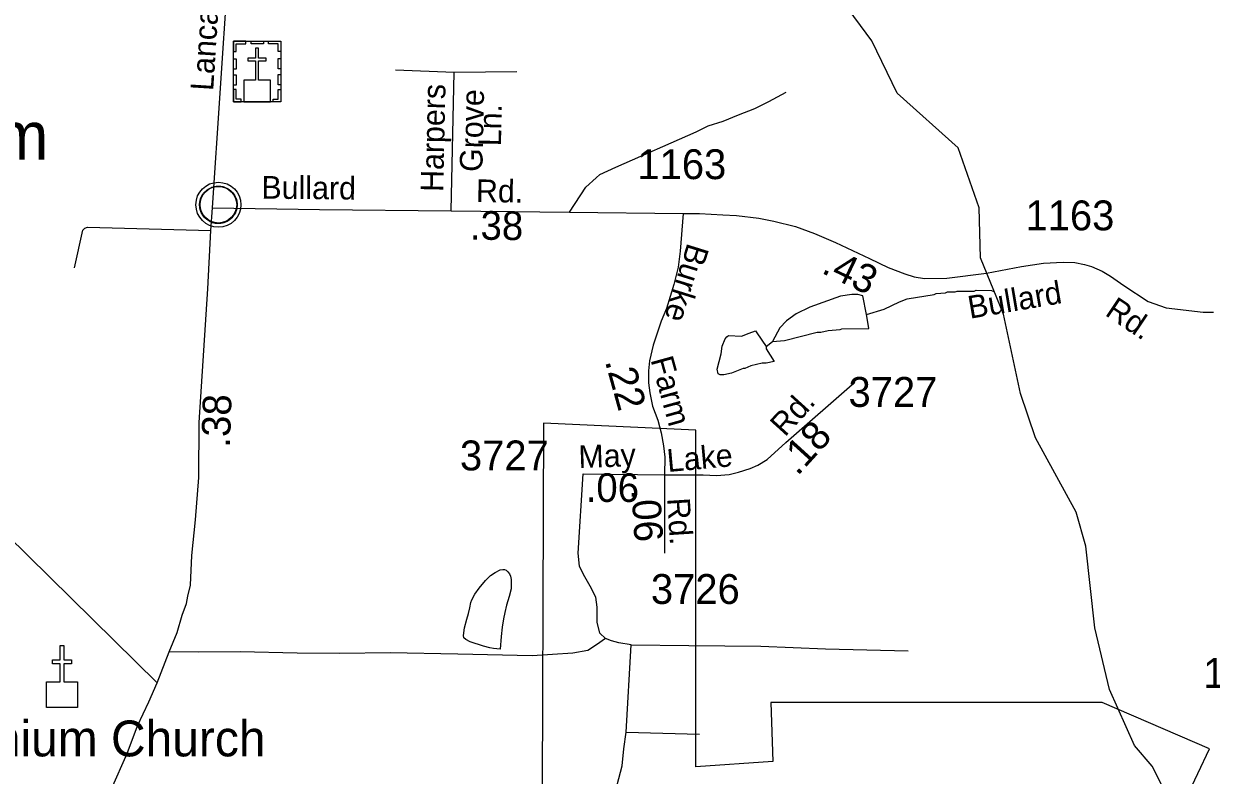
# Model space of a CAD drawing. Extents: x 1547597 to 1699558, y 810033 to 920809.
# Drawn here: x 1580417 to 1585386, y 839204 to 842351 of the extents above; entities that cross this region are included whole.
import ezdxf

# ---------------------------------------------------------------- set-up
doc = ezdxf.new("R2010")
doc.units = 0
for name, color, linetype in [('Exist Boundary Political City Limit New', 7, 'Continuous'), ('Exist Civil Demographics Community CELL', 7, 'Continuous'), ('Exist Civil Demographics Community Label', 7, 'Continuous'), ('Exist Cultural Church CELL', 7, 'Continuous'), ('Exist Cultural Church Label', 7, 'Continuous'), ('Exist Cultural Church with Cemetery CELL', 7, 'Continuous'), ('Exist Hydrographic Creek Single Shore', 7, 'Continuous'), ('Exist Hydrographic Misc Water Feature', 7, 'Continuous'), ('Exist Road Non-System Type 51', 7, 'Continuous'), ('Exist Road Non-System Type 51 Label', 7, 'Continuous'), ('Exist Road Secondary Mileage Hundredths English Label', 7, 'Continuous'), ('Exist Road Secondary Type 51 Attributed', 7, 'Continuous'), ('Exist Road Secondary Type 51 Label', 7, 'Continuous'), ('Exist Road Secondary Type 51 Number Label', 7, 'Continuous'), ('Map Preparation Boundary City Limit Buffer Line', 7, 'Continuous')]:
    doc.layers.add(name, color=color, linetype=linetype)

msp = doc.modelspace()

# ---------------------------------------------------------------- linework, layer by layer
at = {"layer": 'Exist Boundary Political City Limit New'}
msp.add_lwpolyline([(1584886.8, 836342.8), (1584254.2, 836353), (1584179.2, 836450.6), (1584171.7, 838145.2), (1584734, 838165.7), (1584989, 838488.6), (1585379, 839314.3), (1584930.3, 839508.1), (1583543.6, 839509.2), (1583551.1, 839261.5), (1583228.6, 839239), (1583229.7, 840648.8), (1582592.2, 840678.8), (1582585, 838774.6), (1581010.5, 838769.3), (1581018, 838153.8), (1580529.8, 838154.6), (1580542, 837792.4), (1581014.3, 837801.6), (1581014.3, 837482.5), (1580548.2, 837457.9), (1580554.3, 836728.2), (1581993, 836780), (1582030.8, 834859.6)], dxfattribs=at)
at = {"layer": 'Exist Civil Demographics Community CELL'}
msp.add_lwpolyline([(1581153.7, 841605.1), (1581154.7, 841610.7), (1581156.5, 841617.2), (1581159.4, 841624.4), (1581162.3, 841630.2), (1581165.6, 841635.9), (1581169.4, 841641), (1581173.4, 841645.4), (1581178, 841650), (1581183.5, 841654.6), (1581188.9, 841658.3), (1581193.8, 841661.1), (1581198.9, 841663.6), (1581204.3, 841665.9), (1581209.9, 841667.7), (1581214.3, 841668.8), (1581219.1, 841669.6), (1581223.2, 841670.3), (1581229.6, 841670.6), (1581234, 841670.5), (1581239.7, 841670.2), (1581244.6, 841669.5), (1581249.5, 841668.5), (1581254.5, 841667.1), (1581259.7, 841665.1), (1581266.3, 841662.2), (1581272.6, 841658.7), (1581277.7, 841655.2), (1581282.8, 841651.2), (1581286.1, 841648), (1581290.3, 841643.6), (1581294.1, 841638.9), (1581297.2, 841634.4), (1581300.3, 841629.3), (1581302.8, 841624.2), (1581304.8, 841619.2), (1581306.4, 841614.2), (1581307.7, 841609.6), (1581308.8, 841603.5), (1581309.4, 841598.8), (1581309.7, 841592.8), (1581309.5, 841587), (1581308.9, 841581.3), (1581308, 841575.9), (1581306.3, 841569.7), (1581304.4, 841563.9), (1581302.1, 841558.8), (1581299, 841552.8), (1581295.7, 841547.5), (1581292.3, 841542.8), (1581288, 841538), (1581282.7, 841533.1), (1581277.7, 841529), (1581272.7, 841525.5), (1581268.4, 841523), (1581261.6, 841519.8), (1581254.4, 841517.1), (1581248.5, 841515.6), (1581241.9, 841514.3), (1581237.4, 841513.8), (1581233, 841513.6), (1581227.4, 841513.6), (1581223.1, 841514), (1581217.5, 841514.7), (1581211.5, 841516), (1581206.9, 841517.3), (1581201.8, 841519.2), (1581197.2, 841521.2), (1581193.3, 841523.4), (1581186.5, 841527.5), (1581180.9, 841531.8), (1581176, 841536.3), (1581171.5, 841541.1), (1581168.3, 841545.1), (1581165.4, 841549.2), (1581161.3, 841556.3), (1581159.5, 841559.9), (1581157.8, 841563.9), (1581155.2, 841572.1), (1581153.7, 841579.1), (1581153, 841584.3), (1581152.7, 841590.6), (1581152.6, 841595.3), (1581153.2, 841601.8)], close=True, dxfattribs=at)
for centre, radius in [((1581231.3, 841592.7), 94.3), ((1581231, 841592.9), 76.7)]:
    msp.add_circle(centre, radius, dxfattribs=at)
at = {"layer": 'Exist Cultural Church CELL'}
msp.add_lwpolyline([(1580511.5, 839594.7), (1580568.4, 839594.8), (1580568.4, 839671), (1580536.4, 839671), (1580536.4, 839687), (1580568.4, 839687), (1580568.4, 839747.1), (1580584.5, 839747.1), (1580584.5, 839687), (1580616.5, 839687), (1580616.5, 839671), (1580584.5, 839671), (1580584.5, 839594.8), (1580642.1, 839594.7), (1580642.1, 839488.3), (1580511.5, 839488.3)], close=True, dxfattribs=at)
at = {"layer": 'Exist Cultural Church with Cemetery CELL'}
for points in [[(1581293.9, 842277.7), (1581493, 842277.7), (1581493, 842023.1), (1581293.9, 842023.1)], [(1581293.9, 842234.4), (1581305.3, 842234.4), (1581305.3, 842266.6), (1581345.8, 842266.6), (1581345.8, 842277.7), (1581293.9, 842277.7)], [(1581368, 842277.7), (1581419.8, 842277.7), (1581419.8, 842266.3), (1581368, 842266.3)], [(1581493.1, 842234.3), (1581481.7, 842234.3), (1581481.7, 842266.5), (1581441.2, 842266.5), (1581441.2, 842277.6), (1581493.1, 842277.6)], [(1581337, 842023.1), (1581449.2, 842023.1), (1581449.2, 842113.7), (1581398.4, 842113.7), (1581398.4, 842195.2), (1581431.4, 842195.2), (1581431.4, 842206.2), (1581398.4, 842206.2), (1581398.4, 842248.4), (1581386.8, 842248.4), (1581386.8, 842206.2), (1581353.7, 842206.2), (1581353.7, 842195.2), (1581386.8, 842195.2), (1581386.8, 842113.7), (1581337, 842113.7)], [(1581293.9, 842160.2), (1581293.9, 842203.5), (1581305.3, 842203.5), (1581305.3, 842160.2)], [(1581481.7, 842161.2), (1581481.7, 842204.6), (1581493.1, 842204.6), (1581493.1, 842161.2)], [(1581293.9, 842093), (1581293.9, 842136.3), (1581305.3, 842136.3), (1581305.3, 842093)], [(1581481.6, 842095.3), (1581481.6, 842138.6), (1581493, 842138.6), (1581493, 842095.3)], [(1581327, 842023.1), (1581327, 842034.6), (1581305, 842034.6), (1581305, 842075), (1581293.9, 842075), (1581293.9, 842023.1)], [(1581459.9, 842023.1), (1581459.9, 842034.5), (1581481.9, 842034.5), (1581481.9, 842075), (1581493, 842075), (1581493, 842023.1)]]:
    msp.add_lwpolyline(points, close=True, dxfattribs=at)
at = {"layer": 'Exist Hydrographic Creek Single Shore'}
msp.add_lwpolyline([(1585117.5, 838293.2), (1585069.5, 838418.9), (1585088.6, 838592.5), (1585226.6, 838901.5), (1585220.5, 839082.2), (1585139.5, 839241.4), (1585065.5, 839328.3), (1584960.5, 839563.5), (1584898.5, 839820.7), (1584861.6, 840163), (1584821.5, 840304.9), (1584651.5, 840616.9), (1584587.5, 840802.1), (1584516.5, 841135.1), (1584420.5, 841370.1), (1584415.5, 841580.2), (1584326.5, 841831.5), (1584071.5, 842059.9), (1583966.5, 842278.7), (1583843.5, 842445.4)], dxfattribs=at)
at = {"layer": 'Exist Hydrographic Misc Water Feature'}
msp.add_line((1583523.1, 840999.3), (1583549.5, 841019.9), dxfattribs=at)
for points in [[(1583942.9, 841132.8), (1584017.8, 841155.3), (1584082.1, 841186.5), (1584114.3, 841198.1), (1584226.4, 841216.7), (1584234.5, 841220.6), (1584274.5, 841224.1), (1584282.6, 841228), (1584314.6, 841227.6), (1584322.6, 841231.5), (1584394.6, 841230.6), (1584402.6, 841234.5), (1584466.6, 841233.7), (1584478.8, 841227.4)], [(1583942.9, 841132.8), (1583928.3, 841211.3), (1583906.6, 841216.7), (1583882.6, 841217), (1583834.5, 841209.6), (1583705.9, 841163.3), (1583649.6, 841136), (1583609.2, 841106.5), (1583580.9, 841076.9), (1583549.5, 841019.9)], [(1583549.5, 841019.9), (1583600.3, 841024.7), (1583736.7, 841058.9), (1583752.7, 841058.7), (1583782.8, 841066.3), (1583832.9, 841069.7), (1583840.8, 841073.6), (1583953.1, 841074.3), (1583951.1, 841092.2), (1583942.9, 841132.8)], [(1583523.1, 840999.3), (1583523.9, 840989.6), (1583557.8, 840936.2), (1583523.2, 840929.7), (1583507.2, 840929.9), (1583459, 840918.5), (1583434.9, 840906.8), (1583427, 840906.9), (1583378.8, 840887.5), (1583346.7, 840879.9), (1583330.7, 840880.1), (1583322.7, 840884.2), (1583319, 840904.2), (1583335.7, 840968), (1583340.1, 840999.9), (1583352.4, 841031.8), (1583358.6, 841039.7), (1583366.6, 841045.6), (1583420.6, 841042.9), (1583452.7, 841054.5), (1583479.3, 841064.1), (1583484.7, 841056.1), (1583523.1, 840999.3)], [(1582367, 839737.8), (1582340.2, 839744.2), (1582284.4, 839762.8), (1582266.4, 839771.9), (1582258.3, 839779.4), (1582256.8, 839788.7), (1582261.5, 839821.4), (1582271.5, 839857), (1582278.1, 839881.2), (1582283.7, 839904.5), (1582287.8, 839927.8), (1582291.6, 839938.6), (1582304.4, 839961.7), (1582322, 839987.9), (1582349.5, 840019), (1582369.6, 840039.9), (1582389.6, 840053.1), (1582411, 840064.6), (1582421, 840066), (1582428.7, 840065.3), (1582435.4, 840062.6), (1582443.1, 840056.2), (1582449.7, 840047.3), (1582453.7, 840037.4), (1582456, 840023.8), (1582456.6, 840001), (1582455.8, 839984.4), (1582447.5, 839952.9), (1582437.6, 839915.7), (1582429.3, 839885.2), (1582424.1, 839858.9), (1582418.8, 839824.2), (1582414.5, 839785.4), (1582410, 839732.5), (1582382.5, 839734.1), (1582367, 839737.8)]]:
    msp.add_lwpolyline(points, dxfattribs=at)
at = {"layer": 'Exist Road Non-System Type 51'}
for p, q in [((1581973, 842158.2), (1582217.4, 842148)), ((1582204.7, 841566.5), (1582217.4, 842148)), ((1582217.4, 842148), (1582480, 842149.9)), ((1582937.7, 839384.9), (1582958.9, 839750.4)), ((1582937.7, 839384.9), (1583245, 839375.7))]:
    msp.add_line(p, q, dxfattribs=at)
for points in [[(1582699.9, 841561.3), (1582769.5, 841666.4), (1582811.9, 841705.7), (1582828.2, 841719.6), (1582894.7, 841750.5), (1583231, 841897.7), (1583281.4, 841923.1), (1583343.6, 841942.1), (1583408, 841969.2), (1583476.6, 841996.2), (1583535, 842025.5), (1583607.6, 842064.4)], [(1580629.4, 841329.1), (1580663.9, 841486.7), (1580671.8, 841494.7), (1580683.9, 841498.5), (1581199.4, 841485)], [(1582851.9, 839776.2), (1582827, 839798.3), (1582815.9, 839844.5), (1582815.9, 839907.2), (1582810.4, 839949.7), (1582786.4, 839995.8), (1582758.7, 840043.8), (1582742.1, 840078.9), (1582736.5, 840134.2), (1582757.5, 840465.3)], [(1582851.9, 839776.2), (1582814, 839750.4), (1582777.1, 839726.4), (1582714.4, 839715.3), (1582544.6, 839704.2), (1582232.7, 839711.6), (1581949.4, 839717.1), (1581739, 839713.4), (1581560.9, 839715.3), (1581322.8, 839720.8), (1581147.5, 839719), (1581025.7, 839720.8)], [(1582958.9, 839750.4), (1582907.2, 839757.7), (1582875.9, 839767), (1582851.9, 839776.2)], [(1582958.9, 839750.4), (1583199.8, 839746.7), (1583501.5, 839744.8), (1583771.9, 839733.7), (1584118, 839724.5)], [(1582843.6, 838438.1), (1582853.7, 838528.6), (1582853.7, 838637.5), (1582845.4, 838810.9), (1582843.6, 838886.6), (1582861.1, 839006.6), (1582892.5, 839137.6), (1582921.1, 839242.8), (1582928.5, 839314.8), (1582937.7, 839384.9)]]:
    msp.add_lwpolyline(points, dxfattribs=at)
at = {"layer": 'Exist Road Secondary Type 51 Attributed'}
for points in [[(1581206.1, 841579.2), (1581271.2, 842541.9), (1581303.1, 842949.6), (1581313.1, 843180), (1581318.5, 843545.9), (1581315.3, 844018), (1581329.1, 844691.9)], [(1580975.3, 839590.3), (1581025.7, 839720.8), (1581058.9, 839802), (1581079, 839874.8), (1581097.6, 839922.5), (1581103.1, 839953.8), (1581113.8, 839999.8), (1581119.5, 840124.6), (1581135.2, 840272.8), (1581149.8, 840450.8), (1581150.3, 840680.9), (1581187.4, 841241.2), (1581199.4, 841485), (1581206.1, 841579.2)], [(1581206.1, 841579.2), (1581654.8, 841572.2), (1582204.7, 841566.5), (1582699.9, 841561.3), (1583176.2, 841555.8)], [(1583176.2, 841555.8), (1583163.8, 841398.9), (1583155.3, 841331.6), (1583137.6, 841258.5), (1583106.9, 841158.3), (1583083.9, 841105.2), (1583050.3, 841004.3), (1583035.5, 840939.5), (1583030.8, 840897.6), (1583030.8, 840846.9), (1583037.3, 840805), (1583048.5, 840749.6), (1583069.7, 840690), (1583083.6, 840638.1), (1583093.6, 840583.8), (1583099.5, 840535.5), (1583097.7, 840462.3)], [(1583176.2, 841555.8), (1583244, 841555.8), (1583341.9, 841551), (1583399.7, 841547.5), (1583492.3, 841536.9), (1583556, 841523.2), (1583646.5, 841501.5), (1583725.3, 841472.6), (1583814.3, 841434.3), (1583955.9, 841367), (1584034, 841330.5), (1584104.2, 841303.3), (1584143.1, 841290.4), (1584186.7, 841283.9), (1584279.3, 841285.1), (1584446.3, 841305.7), (1584592.8, 841333.4), (1584684.8, 841347.6), (1584766.2, 841352.3), (1584815.1, 841350.5), (1584855.2, 841342.9), (1584884.5, 841333.8), (1584929.3, 841314.5), (1584964.6, 841293.3), (1585021, 841254.4), (1585122.4, 841187.7), (1585197.3, 841160.6), (1585352.1, 841142.3), (1585395.8, 841142.3)], [(1583097.7, 840462.3), (1583259.9, 840461.2), (1583316.3, 840459), (1583368.4, 840463.2), (1583408, 840473.1), (1583456.7, 840488.5), (1583488.5, 840502.6), (1583528, 840526.1), (1583605.6, 840596.7), (1583894.8, 840849.2)], [(1580975.3, 839590.3), (1579804.7, 840742.8)], [(1582757.5, 840465.3), (1583097.7, 840462.3)], [(1583097.7, 840462.3), (1583097.7, 840134.4)], [(1580541.7, 837640.6), (1580531.7, 837808.8), (1580526.2, 838011.5), (1580518.9, 838196.6), (1580520.6, 838315), (1580532.1, 838425.7), (1580541, 838476.2), (1580560.1, 838563.4), (1580582.6, 838637.1), (1580596.1, 838682.8), (1580632, 838786.6), (1580659.7, 838849.5), (1580724.4, 839003.5), (1580776.4, 839127.4), (1580784.3, 839147.4), (1580849.3, 839294.9), (1580892.2, 839411.2), (1580940.7, 839511.1), (1580975.3, 839590.3)]]:
    msp.add_lwpolyline(points, dxfattribs=at)
at = {"layer": 'Map Preparation Boundary City Limit Buffer Line'}
msp.add_lwpolyline([(1584886.8, 836342.8), (1584254.2, 836353), (1584179.2, 836450.6), (1584171.7, 838145.2), (1584734, 838165.7), (1584989, 838488.6), (1585379, 839314.3), (1584930.3, 839508.1), (1583543.6, 839509.2), (1583551.1, 839261.5), (1583228.6, 839239), (1583229.7, 840648.8), (1582592.2, 840678.8), (1582585, 838774.6), (1581010.5, 838769.3), (1581018, 838153.8), (1580529.8, 838154.6), (1580542, 837792.4), (1581014.3, 837801.6), (1581014.3, 837482.5), (1580548.2, 837457.9), (1580554.3, 836728.2), (1581993, 836780), (1582030.8, 834859.6)], dxfattribs=at)

# ---------------------------------------------------------------- texts
at = {"layer": 'Exist Civil Demographics Community Label'}
msp.add_text('Capernium', height=200, dxfattribs=at).set_placement((1579211.8, 841781.6))
at = {"layer": 'Exist Cultural Church Label'}
msp.add_text('Capernium Church', height=150, dxfattribs=at).set_placement((1579744.9, 839283))
at = {"layer": 'Exist Road Non-System Type 51 Label'}
for s, p in [('Harpers', (1582172, 841645.7)), ('Grove', (1582335.8, 841729.5)), ('Ln.', (1582413.6, 841837))]:
    msp.add_text(s, height=95, rotation=88.7562, dxfattribs=at).set_placement(p)
at = {"layer": 'Exist Road Secondary Mileage Hundredths English Label'}
for s, rotation, p in [('.38', 359.4008, (1582283.3, 841446.7)), ('.43', 334.4756, (1583750.3, 841309)), ('.22', 285.5097, (1582848.1, 840937.4)), ('.38', 88.1821, (1581279.4, 840574.6)), ('.18', 47.7545, (1583654.7, 840454.2)), ('.06', 359.9405, (1582768.4, 840348.4)), ('.06', 273.6481, (1582959.3, 840400.3))]:
    msp.add_text(s, height=120, rotation=rotation, dxfattribs=at).set_placement(p)
at = {"layer": 'Exist Road Secondary Type 51 Label'}
for s, rotation, p in [('Lancaster', 86.3654, (1581209.3, 842067.8)), ('Bullard', 359.4008, (1581410.9, 841618.5)), ('Rd.', 359.4008, (1582308.8, 841603.8)), ('Burke', 252.7598, (1583195.1, 841436.4)), ('Bullard', 9.6425, (1584376.3, 841115.1)), ('Rd.', 326.2244, (1584937.4, 841132.4)), ('Farm', 285.5097, (1583039.2, 840943.8)), ('Rd.', 47.7545, (1583602.2, 840617.5)), ('May', 2.0475, (1582739.6, 840489.9)), ('Lake', 5.1996, (1583112.4, 840473.4)), ('Rd.', 273.6481, (1583109, 840363))]:
    msp.add_text(s, height=95, rotation=rotation, dxfattribs=at).set_placement(p)
at = {"layer": 'Exist Road Secondary Type 51 Number Label'}
for s, p in [('1163', (1582984.8, 841699.9)), ('1163', (1584608.9, 841485.6)), ('3727', (1583868.2, 840746.3)), ('3727', (1582242.1, 840480.5)), ('3726', (1583041.2, 839921.2)), ('1101', (1585352.4, 839569.6))]:
    msp.add_text(s, height=125, dxfattribs=at).set_placement(p)

doc.saveas('drawing.dxf')
